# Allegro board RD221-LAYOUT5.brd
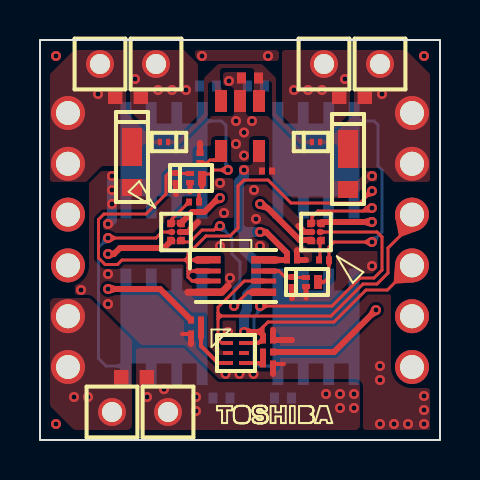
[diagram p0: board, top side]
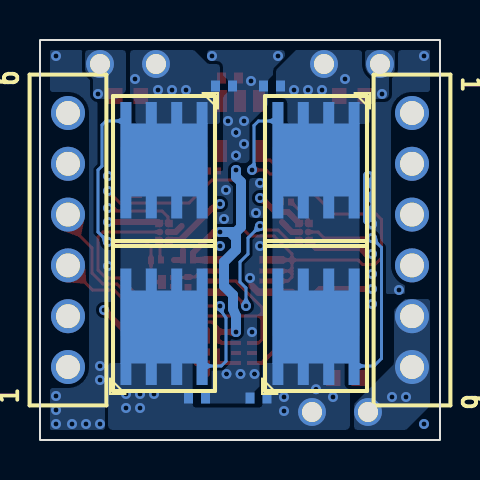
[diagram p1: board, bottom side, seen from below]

Outline 20 x 20 mm; copper layers: TOP, CONDUCTIVE2, CONDUCTIVE3, BOTTOM. Coordinates in mm from the lower left corner of the outline.
Outline path: rectangle 0,0 20,20

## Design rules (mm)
constraint set DEFAULT: 

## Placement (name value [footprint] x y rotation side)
C501  -  [KC00051KD]  10.5 18.1 180 top
C502  -  [KC00540KD]  8 14.1 90 top
C503  -  [KC00540KD]  11.35 13.45 0 top
C504  -  [KC00051KD]  8.4 17.7 0 bottom
C505  -  [KC00051KD]  12.15 2.1 180 bottom
C506  -  [KC00540KD]  11.4 5 0 top
C507  -  [KC00051KD]  10.8 17.7 180 bottom
C508  -  [KC00051KD]  9.07 2.1 0 bottom
C509  -  [KC00540KD]  12.6 9 0 top
CN501  -  [CU12000TD]  1.4 16.35 270 bottom
CN502  -  [CU12000TD]  18.6 3.65 90 bottom
D501  -  [MM02020KD]  4.6 13.9 90 top
D502  -  [MM02020KD]  15.4 13.8 90 top
D503  -  [KC10480CD]  6.2 14.9 0 top
D504  -  [KC10480CD]  13.8 14.9 180 top
DP501  -  [DP002X0KD]  3 18.8 0 top
DP502  -  [DP002X0KD]  5.8 18.8 0 top
DP503  -  [DP002X0KD]  17 18.8 0 top
DP504  -  [DP002X0KD]  14.2 18.8 0 top
DP505  -  [DP002X0KD]  6.4 1.4 0 top
DP506  -  [DP002X0KD]  3.6 1.4 0 top
IC501  -  [MM00631KD]  10 15.7 180 top
IC502  -  [DIC8T60KD]  9.8 8.2 270 top
IC503  -  [LA10251KD]  9.8 4.35 270 top
IC504  -  [BA10620KD]  6.8 10.4 270 top
IC505  -  [BA10620KD]  13.8 10.4 90 top
JP501  -  [KC00081KD]  4.4 17.2 0 top
JP502  -  [KC00081KD]  15.6 17.2 180 top
JP503  -  [KC00081KD]  4.7 3.1 180 top
NOREF  -  []  8 0 0 top
Q501  -  [LA10710KD]  7.8 13.1 0 top
Q502  -  [LA10710KD]  13.6 7.9 0 top
Q503  -  [SN10261KD]  6.2 13.45 0 bottom
Q504  -  [SN10261KD]  6.2 6.2 180 bottom
Q505  -  [SN10261KD]  13.8 13.45 0 bottom
Q506  -  [SN10261KD]  13.8 6.2 180 bottom
R501  -  [KC00540KD]  7.8 6 0 top
R502  -  [KC00540KD]  7.8 5.3 180 top
R503  -  [KC00540KD]  11.4 4.4 180 top
R504  -  [KC00540KD]  11.4 3.8 0 top
R505  -  [KC00540KD]  7.7 11.9 180 top
R506  -  [KC00540KD]  14.2 9 180 top
R507  -  [KC00540KD]  6.8 13.1 270 top
R508  -  [KC00540KD]  12.6 7.9 270 top

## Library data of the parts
C501 C504 C505 C507 C508 = DP0000016125
C502 C503 = DP0007093000
C506 C509 = DP0000015403
CN501 CN502 = DP0010563000
D501 = DP0010557000
D502 = DP0010580000
D503 D504 = DP0010560000
DP501-DP506 = DP9000817000
IC501 = DP0010585000
IC502 = DP0001429000
IC503 = DP0010561000
IC504 = DP0010596000
IC505 = DP0010597000
JP501-JP503 = DP0001376000
Q501 = DP0010564000
Q502 = DP0010513000
Q503-Q506 = DP0010567000
R501 = DP0000151167
R502 = DP0000151152
R503 = DP0000152120
R504 = DP0000151132
R505 R506 = DP0000155124
R507 R508 = DP0002867000

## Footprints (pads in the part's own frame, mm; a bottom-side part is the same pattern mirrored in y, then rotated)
BA10620KD
  round 0.325 smd: A1(-0.4,-0.2) A2(-0.4,0.2) B1(0,-0.2) B2(0,0.2) C1(0.4,-0.2) C2(0.4,0.2)
CU12000TD
  round 1.7 hole 1.2: 1(0,0) 2(2.54,0) 3(5.08,0) 4(7.62,0) 5(10.16,0) 6(12.7,0)
DIC8T60KD
  rect 0.375x1.24 smd: 1(-0.812,-1.385) 4(0.812,-1.385) 5(0.812,1.385) 8(-0.812,1.385)
  rect 0.25x1.24 smd: 2(-0.25,-1.385) 3(0.25,-1.385) 6(0.25,1.385) 7(-0.25,1.385)
DP002X0KD
  round 1.397 hole 1: 1(0,0)
KC00051KD
  rect 0.45x0.55 smd: 1(-0.425,0) 2(0.425,0)
KC00081KD
  rect 0.72x0.8 smd: 1(-0.64,0) 2(0.64,0)
KC00540KD
  rect 0.3x0.35 smd: 1(-0.25,0) 2(0.25,0)
KC10480CD
  rect 0.21x0.32 smd: A(-0.205,0) C(0.205,0)
LA10251KD
  rect 0.2x0.5 smd: 1(-0.5,-0.4) 2(0,-0.4) 3(0.5,-0.4) 4(0.5,0.4) 5(0,0.4) 6(-0.5,0.4)
LA10710KD
  rect 0.4x0.7 smd: D(0.3,0)
  rect 0.4x0.25 smd: G(-0.3,0.225) S(-0.3,-0.225)
MM00631KD
  rect 0.6x1.1 smd: 1(-0.95,-1.25) 2(0,-1.25) 3(0.95,-1.25) 4(0.95,1.25) 5(-0.95,1.25)
MM02020KD
  rect 0.85x1 smd: A(-1.275,0)
  rect 1.9x1 smd: C(0.75,0)
SN10261KD
  rect 0.55x1.1 smd: 1(-1.905,-2.9) 2(-0.635,-2.9) 3(0.635,-2.9) 4(1.905,-2.9)
  custom 1.09x1.09 smd: 5(0,0)

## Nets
GND: C501.2 C502.2 C503.2 C504.2 C505.2 C506.2 C507.2 C508.2 C509.2 CN501.3 CN501.4 D501.A D502.A IC501.2 IC502.4 IC503.2 IC504.B2 IC505.B2 Q501.S Q502.S R502.2 R504.2 R507.2 R508.2
VINA: CN501.1 CN501.2 D501.C D503.A DP501.1 JP501.1 R501.1
VINB: CN502.5 CN502.6 D502.C D504.A DP503.1 JP502.1 R503.1
EN20V: CN502.1 IC502.1 IC502.2 IC502.3 Q501.G R507.1
FLAG: CN502.4 IC502.6 IC503.1
LDO-VOUT: C503.1 C506.1 C509.1 CN502.3 IC501.5 IC502.8 IC503.6
SIG188: IC504.A1 R505.2
SIG189: IC505.B1 Q506.4
SIG190: IC505.A1 R506.2
SIG191: C507.1 DP504.1 IC505.A2 JP502.2 Q505.1 Q505.2 Q505.3
SIG192: C502.1 IC501.4
SIG193: C501.1 D503.C D504.C IC501.1 IC501.3
SIG194: IC503.4 R503.2 R504.1
SIG201: C505.1 C508.1 DP505.1 IC504.C1 IC505.C1 JP503.1 Q504.1 Q504.2 Q504.3 Q506.1 Q506.2 Q506.3
SIG202: IC502.7 Q502.G R508.1
SIG203: C504.1 DP502.1 IC504.A2 JP501.2 Q503.1 Q503.2 Q503.3
SIG204: Q501.D Q503.4 R505.1
SIG205: Q503.5 Q504.5
SIG206: IC504.B1 Q504.4
SIG207: IC502.5 IC504.C2
SIG208: Q505.5 Q506.5
SIG209: Q502.D Q505.4 R506.1
SIG211: IC503.3 R501.2 R502.1
VCT5V: CN502.2 IC505.C2
VOUT: CN501.5 CN501.6 DP506.1 JP503.2

Pads without a net: IC503 5

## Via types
v1: diameter 0.5, hole 0.25, TOP to BOTTOM, 77 vias

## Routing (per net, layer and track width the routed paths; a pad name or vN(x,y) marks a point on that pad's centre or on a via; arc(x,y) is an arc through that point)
GND: length 22.1
  TOP w0.2: 12.2,3.8 R504.2 ; R502.2 7.1,5.3
  TOP w0.25: Q502.S 13.3,7.1 ; Q501.S 7.5,12.4
  TOP w0.3: IC505.B2 13.22,10.4 12.92,10.7 ; R502.2 7.55,4.8 ; 7.9,10.9 7.4,10.4 IC504.B2 ; C502.2 8,14.85 ; R504.2 11.65,3.3 ; 12.85,9.49 C509.2 13.3,9 ; 11.65,5.5 C506.2 12.6,5 ; R508.2 12.6,7.1 ; R507.2 6.8,12.3
  TOP w0.35: 7.4,7.39 IC502.4 9.09,7.39 9.41,7.71
  CONDUCTIVE2 w0.15: 6.15,0.57 6.67,0.57 ; 3.35,0.57 3.9,0.57
  CONDUCTIVE2 w1: CN501.3 2.5,11.27 ; CN501.3 CN501.4 ; CN501.3 1.4,12.45 ; CN501.4 2.4,8.73 ; CN501.4 1.4,7.55
  CONDUCTIVE3 w0.15: 6.17,0.57 6.62,0.57
  BOTTOM w0.5: v1(3.6,13.2) v1(3.6,12.5) v1(3.6,11.8) 3.6,11 v1(3.4,10.8)
  vias: v1(0.8,19.2) v1(0.8,0.8) v1(2.05,7.5) v1(3.4,8.3) v1(3.4,6.8) v1(8.1,19.2) v1(9,12.85) v1(9,9.7) v1(9.2,11.35) v1(9.28,3.3) v1(9.45,17.95) v1(9.4,5.4) v1(9.5,8.1) v1(9.8,15.95) v1(9.8,14.8) v1(9.97,3.3) v1(10.2,15.38) v1(10.2,14.22) v1(10.6,15.95) v1(10.7,12.5) v1(10.68,3.3) v1(10.8,11.05) v1(11,9.7) v1(11.4,19.2) v1(16.6,13.2) v1(16.6,8.7) v1(17,3.7) v1(17,3) v1(17,0.8) v1(17.7,0.8) v1(18.4,0.8) v1(19.2,19.2) v1(19.2,2.2) v1(19.2,1.5) v1(19.2,0.8)
VINA: length 15.2
  TOP w0.3: R501.1 6,7.55 v1(3.4,7.55)
  CONDUCTIVE3 w0.6: v1(3.4,7.55) 3.05,7.55 2.65,7.95 2.65,17.05 v1(2.9,17.3)
VINB: length 17.2
  TOP w0.3: v1(16.8,6.5) 14.7,4.4 R503.1
  CONDUCTIVE3 w0.6: v1(17.1,17.3) 17.35,16.79 17.35,6.85 17,6.5 v1(16.8,6.5)
EN20V: length 41.2
  TOP w0.15: 7.83,7.95 7.6,7.95 7.4,8.15 7.4,8.3 ; 7.55,8.45 7.4,8.6 ; 7.55,8.45 7.4,8.3 ; 7.55,8.45 7.83,8.45 ; 7.55,8.45 7.4,8.45 ; 7.4,8.6 7.4,8.85 ; 7.4,8.6 7.4,8.45 ; 7.4,8.85 7.4,9 ; 7.4,8.85 7.55,9 ; 7.4,8.85 7.25,9 ; 7.4,9 7.55,9 ; 7.4,9 7.4,9.15 ; 7.4,9 7.25,9 ; 7.4,8.3 7.4,8.45 ; 7.42,13.32 7.1,13.32 R507.1 6.45,13.35 6.3,13.2 6.3,12.3 5.3,11.3 3.2,11.3 2.92,11.03 2.92,9.1 3.25,8.78 3.88,8.78 4.1,9 7.25,9 ; 7.55,9 7.87,9 ; 7.55,9 7.4,9.15 ; v1(16.6,12.45) 16,11.85 12.55,11.85 11.4,13 10.2,13 9.9,12.7 9.9,10.6 9.5,10.2 8.3,10.2 7.4,9.3 7.4,9.15 ; 7.25,9 7.4,9.15
  TOP w0.25: Q501.G 7.42,13.32 ; 7.83,7.95 IC502.3 ; 7.83,8.45 IC502.2
  TOP w0.35: 7.87,9 8.4,9
  CONDUCTIVE2 w0.15: CN502.1 17.25,5 17.25,9.9 16.7,10.45 16.35,10.45 16.05,10.75 16.05,11.9 v1(16.6,12.45)
FLAG: length 18.2
  TOP w0.15: 8.9,6.2 9.05,6.2 ; 8.9,6.2 8.9,6.05 ; 8.9,6.2 8.9,6.35 ; 9.05,6.2 8.9,6.05 ; 9.05,6.2 8.9,6.35 ; 9.05,6.2 14.55,6.2 16.15,7.8 16.85,7.8 17.4,8.35 17.4,9.6 18,10.2 CN502.4 ; 8.9,6.05 8.9,5.03 9.07,4.85 9.25,4.85 ; 10.69,7.95 10.22,7.95 8.9,6.63 8.9,6.35
  TOP w0.2: 9.25,4.85 IC503.1
  TOP w0.25: IC502.6 10.69,7.95
LDO-VOUT: length 24.9
  TOP w0.15: CN502.3 17.37,7.5 16.3,7.5 14.7,5.9 11.4,5.9 11.15,5.65 ; 11.15,5.65 11.15,5.35 ; 11.15,5.65 10.9,5.4
  TOP w0.2: IC503.6 10.9,4.85 C506.1
  TOP w0.3: 11.79,9 C509.1 12.35,9.36 11.31,10.4 v1(11,10.4) ; v1(10.2,5.4) 11,5.4 11.15,5.25 C506.1
  TOP w0.35: 11.79,9 11.19,9
  BOTTOM w0.5: v1(10.2,5.4) 10.2,6.2 10.35,6.55 10.35,7.25 10.8,7.7 10.8,8.9 10.2,9.5 10.2,10.1 ; 10.2,10.4 9.95,10.65 9.95,12.9 10.2,13.15 v1(10.2,13.5) ; 10.2,10.4 10.2,10.1 ; 10.2,10.4 10.5,10.4 ; 10.2,10.1 10.5,10.4 ; 10.5,10.4 v1(11,10.4)
SIG188: length 1.5
  TOP w0.15: R505.2 6.6,11.05 IC504.A1
SIG189: length 15.8
  TOP w0.15: IC505.B1 16.85,10.4 17.1,10.15 17.1,8.5 16.7,8.1 16,8.1 14.6,6.7 v1(11,6.7)
  BOTTOM w0.15: 11.67,3.7 10.94,3.7 10.7,3.94 10.7,6.1 10.9,6.4 v1(11,6.7)
  BOTTOM w0.3: 11.67,3.7 11.89,3.7
SIG190: length 1
  TOP w0.15: IC505.A1 14,9.2 R506.2
SIG191: length 9.9
  TOP w0.3: v1(11,11.8) 11.4,11.58 12.98,10 IC505.A2
  CONDUCTIVE3 w0.6: v1(11,11.8) 11.3,11.8 11.9,12.4 11.9,16.7 v1(12.7,17.5)
  vias: v1(13.4,17.5) v1(14.1,17.5) v1(15.25,18.05)
SIG192: length 1.1
  TOP w0.15: 8.02,13.85 8.35,13.85 8.5,14 8.77,14
  TOP w0.2: 8.77,14 9,14
  TOP w0.3: C502.1 8.02,13.85
SIG194: length 1.6
  TOP w0.2: IC503.4 10.9,3.85 R504.1
  TOP w0.3: R503.2 R504.1
SIG201: length 28.1
  TOP w0.3: v1(3.4,9.3) 3.7,9.3 4,9.6 6.2,9.6 IC504.C1 ; v1(16.6,10.9) 14.1,10.9 IC505.C1
  CONDUCTIVE3 w0.5: v1(5.35,2.15) 5.35,8.35 ; 5.35,8.35 5.35,9.1 ; 5.35,8.35 5.9,8.9 ; 5.35,9.1 5.55,8.9 5.9,8.9 ; 5.35,9.1 5.15,9.3 v1(3.4,9.3) ; 5.9,8.9 11.3,8.9 13.3,10.9 v1(16.6,10.9)
  vias: v1(6.2,2.54) v1(7.8,2.15) v1(7.8,1.45) v1(14.3,2.3) v1(15,2.3) v1(15,1.6) v1(15.7,2.3) v1(15.7,1.6)
SIG202: length 2.2
  TOP w0.15: 11.77,8.45 11.95,8.45 12.25,8.15 R508.1 12.9,8.12 13.22,8.12
  TOP w0.25: Q502.G 13.22,8.12 ; 11.77,8.45 IC502.7
SIG203: length 8.9
  TOP w0.3: IC504.A2 7.6,11.4 8.22,11.4 8.74,11.92 v1(9,12.1)
  CONDUCTIVE3 w0.6: v1(9,12.1) 8.6,12.1 8.2,12.5 8.2,16.6 v1(7.3,17.5)
  vias: v1(4.75,18.05) v1(5.9,17.5) v1(6.6,17.5)
SIG204: length 6.2
  TOP w0.15: 8.1,13.3 8.5,13.3 8.7,13.5 v1(9.4,13.5) ; 7.95,11.99 7.95,12.35 8.1,12.5 8.1,12.84
  TOP w0.3: R505.1 7.95,11.99
  TOP w0.4: 8.1,12.84 Q501.D
  BOTTOM w0.15: 8.33,15.95 9.07,15.95 9.3,15.72 9.3,13.8 v1(9.4,13.5)
  BOTTOM w0.3: 8.11,15.95 8.33,15.95
SIG206: length 11.1
  TOP w0.15: IC504.B1 6.1,10.4 5.8,10.1 v1(3.4,10.1)
  BOTTOM w0.15: 4.07,3.7 3.3,3.7 2.92,4.08 2.92,9.62 v1(3.4,10.1)
  BOTTOM w0.3: 4.07,3.7 4.29,3.7
SIG207: length 8.6
  TOP w0.15: v1(9.7,6.7) 10.39,7.39 10.65,7.39 ; v1(9,10.7) 8.7,10.5 8.1,10.5 7.5,9.9 7.25,9.9 IC504.C2
  TOP w0.37: 10.65,7.39 IC502.5
  BOTTOM w0.15: v1(9.7,6.7) 9.7,7.6 10,7.9 10,8.9 9.6,9.3 9.6,10.1 v1(9,10.7)
SIG209: length 11.8
  TOP w0.15: 14.45,9.02 14.45,9.65 14.7,9.9 v1(16.6,9.9) ; Q502.D 14.2,7.9 14.45,8.15 14.45,8.9
  TOP w0.3: 14.45,9.02 R506.1 14.45,8.9
  BOTTOM w0.15: 15.93,15.95 16.7,15.95 16.9,15.75 16.9,13.7 17.1,13.5 17.1,10.4 v1(16.6,9.9)
  BOTTOM w0.3: 15.71,15.95 15.93,15.95
SIG211: length 3
  TOP w0.2: 8.05,5.19 8.05,4.7 8.9,3.85 IC503.3
  TOP w0.3: R501.2 R502.1 8.05,5.19
VCT5V: length 10.3
  TOP w0.15: 16.15,11.45 16.45,11.45 v1(16.6,11.6) 16.3,11.6 16.15,11.45 ; 16.15,11.45 13.9,11.45 13.6,11.15 IC505.C2
  CONDUCTIVE2 w0.15: CN502.2 17.65,7.14 17.65,10.55 v1(16.6,11.6)
VOUT:
  vias: v1(1.7,2.15) v1(2.4,2.15)

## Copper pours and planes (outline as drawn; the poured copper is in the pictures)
GND on TOP: outline of 290 points within 1.74,0.5 19.5,18.4
GND on TOP: outline of 88 points within 7.93,7.4 13.6,12.78
GND on TOP: 8.02,18.95 7.92,18.99 7.79,19.12 7.75,19.22 7.75,19.35 7.79,19.46 7.9,19.5 11.8,19.5 11.91,19.46 11.95,19.35 11.95,19.1 11.91,18.99 11.8,18.95
GND on TOP: 3.79,10.35 3.77,10.35 3.75,10.36 3.5,10.49 3.4,10.5 3.3,10.5 3.19,10.54 3.15,10.65 3.15,10.9 3.16,10.93 3.17,10.95 3.27,11.05 3.3,11.07 3.32,11.07 5.3,11.07 5.39,11.09 5.46,11.14 6.46,12.14 6.52,12.24 6.53,12.3 6.53,12.35 6.57,12.46 6.67,12.5 7.55,12.5 7.6,12.48 7.62,12.43 7.62,12.35 7.6,12.3 7.55,12.28 7.33,12.28 7.17,12.21 7.1,12.05 7.1,11.9 7.09,11.87 7.08,11.85 6.44,11.21 6.4,11.17 6.38,11.16 6.26,11.08 6.21,10.94 6.21,10.91 6.2,10.89 6.19,10.86 5.7,10.37 5.67,10.36 5.64,10.35
GND on TOP: 7.44,10.25 7.38,10.27 7.36,10.33 7.36,10.58 7.38,10.64 7.39,10.67 7.4,10.7 7.42,10.72 7.51,10.79 7.8,11.08 7.83,11.09 7.86,11.1 8.22,11.1 8.34,11.12 8.43,11.19 8.89,11.64 8.92,11.66 9.11,11.71 9.4,12.15 9,12.5 8.75,12.5 8.64,12.54 8.6,12.65 8.6,12.89 8.61,12.95 8.64,12.99 8.71,13.06 8.81,13.1 9.53,13.1 9.63,13.06 9.68,12.95 9.68,11.19 9.67,11.16 9.65,11.14 9.6,11.11 9.55,11.1 9,11.1 8.8,11.05 8.65,10.9 8.62,10.82 8.6,10.78 8.58,10.74 8.53,10.72 8.1,10.72 8.01,10.71 7.94,10.66 7.58,10.3 7.53,10.26 7.47,10.25
GND on BOTTOM: 8.9,11.1 8.79,11.14 8.75,11.25 8.75,11.55 8.79,11.66 8.9,11.7 9,11.7 9.28,11.82 9.4,12.1 9.4,12.1 9.28,12.38 9,12.5 8.9,12.5 8.79,12.54 8.75,12.65 8.75,12.95 8.79,13.06 8.9,13.1 9.4,13.1 9.51,13.06 9.55,12.95 9.55,12.1 9.55,12.1 9.55,11.25 9.51,11.14 9.4,11.1
GND on BOTTOM: 9.43,1.82 9.32,1.87 9.28,1.98 9.28,2.42 9.05,2.65 9.03,2.68 9.03,2.71 9.03,3.78 9.04,3.83 9.13,3.87 9.15,3.91 9.15,6.12 9.13,6.18 9.07,6.2 8.82,6.2 8.77,6.22 8.75,6.28 8.75,10.26 8.78,10.32 8.85,10.33 8.9,10.31 9.11,10.26 9.15,10.24 9.35,10.03 9.37,10 9.38,9.98 9.38,9.3 9.39,9.21 9.44,9.14 9.75,8.83 9.77,8.8 9.78,8.78 9.78,8.02 9.77,8 9.75,7.97 9.54,7.76 9.49,7.69 9.47,7.6 9.47,7.13 9.46,7.09 9.35,6.9 9.36,6.49 9.72,6.3 9.78,6.28 9.8,6.23 9.8,5.4 9.98,5.06 10.44,5.03 10.47,4.97 10.47,3.94 10.49,3.85 10.54,3.78 10.78,3.54 10.85,3.49 10.94,3.48 11.35,3.48 11.4,3.45 11.42,3.4 11.42,2.65 11.5,2.46 11.7,2.38 11.88,2.38 11.93,2.35 11.95,2.3 11.95,1.9 11.93,1.85 11.88,1.82
GND on BOTTOM: 1.83,7.3 1.78,7.32 1.75,7.38 1.75,7.69 1.77,7.73 1.8,7.76 2.28,8.15 2.45,8.75 2.45,11.25 2.45,11.29 2.45,13.79 2.45,13.83 2.45,16.33 2.15,17.09 1.4,17.4 0.65,17.4 0.54,17.44 0.5,17.55 0.5,19.43 0.52,19.48 0.57,19.5 1.95,19.5 2.06,19.46 2.1,19.35 2.1,18.51 2.14,18.36 2.19,18.3 2.38,18.11 2.39,18.09 2.4,18.06 2.4,17.3 2.52,17.02 2.8,16.9 3.17,16.9 3.23,16.88 3.25,16.82 3.25,13.53 3.27,13.47 3.33,13.45 3.58,13.45 3.63,13.43 3.65,13.38 3.65,10.65 3.61,10.54 3.5,10.5 3.4,10.5 3.16,10.42 3.01,10.2 2.96,9.99 2.94,9.95 2.77,9.78 2.72,9.71 2.7,9.62 2.7,7.38 2.68,7.32 2.62,7.3
GND on BOTTOM: 16.9,0.5 16.79,0.54 16.75,0.65 16.75,6.03 16.77,6.08 16.82,6.1 17.2,6.51 16.8,6.9 16.5,6.9 16.39,6.94 16.35,7.05 16.35,9.43 16.37,9.48 16.43,9.5 16.6,9.5 16.84,9.58 16.99,9.79 17.04,10.01 17.06,10.05 17.26,10.24 17.3,10.3 17.32,10.38 17.32,13.5 17.31,13.59 17.26,13.66 17.15,13.77 17.13,13.8 17.12,13.82 17.13,16.84 17.14,16.88 17.41,17.05 17.5,17.3 17.5,17.96 17.51,17.99 17.52,18.01 17.81,18.3 17.88,18.4 17.9,18.51 17.9,19.35 17.89,19.41 17.91,19.47 17.97,19.5 19.43,19.5 19.48,19.48 19.5,19.43 19.5,17.55 19.46,17.44 19.35,17.4 18.6,17.4 17.86,17.09 17.55,16.35 17.55,3.65 17.86,2.91 18.6,2.6 19.35,2.6 19.46,2.56 19.5,2.45 19.5,0.57 19.48,0.52 19.43,0.5
GND on BOTTOM: 10.43,10.8 10.37,10.82 10.35,10.88 10.35,12.65 10.36,12.68 10.37,12.71 10.48,12.82 10.57,12.95 10.6,13.1 10.6,13.5 10.41,13.84 10.02,13.86 9.98,13.85 9.74,13.85 9.68,13.86 9.63,13.89 9.57,13.96 9.54,14 9.53,14.06 9.53,15.58 9.53,15.72 9.51,15.81 9.46,15.88 8.64,16.7 8.61,16.74 8.6,16.93 8.6,17.94 8.56,18.04 8.37,18.23 8.36,18.25 8.35,18.28 8.35,18.44 8.31,18.59 8.26,18.65 7.79,19.12 7.75,19.22 7.75,19.35 7.79,19.46 7.9,19.5 11.5,19.5 11.61,19.46 11.65,19.35 11.65,19.16 11.61,19.06 11.54,18.99 11.44,18.95 11.15,18.95 11,18.91 10.89,18.8 10.85,18.65 10.85,18.28 10.84,18.25 10.83,18.23 10.64,18.04 10.6,17.94 10.6,17.46 10.61,17.4 10.64,17.36 10.81,17.19 10.84,17.15 10.85,13.53 10.87,13.47 10.93,13.45 11.18,13.45 11.23,13.43 11.25,13.38 11.25,12.35 11.21,12.24 11.1,12.2 11,12.2 10.6,11.8 11,11.4 11.1,11.4 11.21,11.36 11.25,11.25 11.25,10.95 11.21,10.84 11.1,10.8
GND on CONDUCTIVE2: outline of 156 points within 0.5,0.5 19.5,19.5 ; 22 cut-outs
GND on CONDUCTIVE3: outline of 114 points within 0.5,0.5 19.5,10.5 ; 6 cut-outs
GND on CONDUCTIVE3: outline of 103 points within 0.5,9.3 19.5,19.5 ; 7 cut-outs
VINA on BOTTOM: 2.8,17.05 2.62,17.12 2.55,17.3 2.55,18.09 2.51,18.19 2.29,18.41 2.25,18.51 2.25,19.35 2.29,19.46 2.4,19.5 3.6,19.5 3.7,19.47 3.75,19.38 3.75,19.35 3.75,18.8 3.67,18.46 3.37,18.12 3.35,18.01 3.35,17.2 3.31,17.09 3.2,17.05
VINB on BOTTOM: 16.16,17.05 16.06,17.09 15.74,17.41 15.7,17.51 15.7,19.35 15.74,19.46 15.85,19.5 17.6,19.5 17.71,19.46 17.75,19.35 17.75,18.51 17.71,18.41 17.39,18.09 17.35,17.99 17.35,17.3 17.32,17.18 17.23,17.08 17.1,17.05
LDO-VOUT on TOP: 10.1,13.25 9.99,13.29 9.95,13.4 9.95,13.6 9.99,13.71 10.1,13.75 10.49,13.75 10.55,13.76 10.59,13.79 10.61,13.81 10.65,13.91 10.65,14.75 10.69,14.86 10.8,14.9 11.1,14.9 11.21,14.86 11.25,14.75 11.25,13.4 11.21,13.29 11.1,13.25
SIG191 on TOP: 13.01,15.35 12.98,15.36 12.95,15.37 12.12,16.2 12.11,16.23 12.1,16.26 12.1,19.35 12.14,19.46 12.25,19.5 15.35,19.5 15.46,19.46 15.5,19.35 15.5,16.41 15.46,16.31 14.54,15.39 14.44,15.35
SIG191 on BOTTOM: 11.15,15.8 11.04,15.84 11,15.95 11,18.65 11.04,18.76 11.15,18.8 11.54,18.8 11.64,18.84 12.26,19.46 12.36,19.5 15.35,19.5 15.46,19.46 15.5,19.35 15.5,17.17 15.48,17.12 15.29,17 15.23,16.82 15.23,15.95 15.19,15.84 15.08,15.8
SIG193 on TOP: 6.38,14.8 6.32,14.82 6.3,14.88 6.3,14.93 6.32,14.98 6.38,15 6.83,15 6.88,15.01 6.93,15.04 8.16,16.27 8.19,16.32 8.2,16.37 8.2,18.04 8.24,18.14 8.86,18.76 8.96,18.8 11.04,18.8 11.14,18.76 11.76,18.14 11.8,18.04 11.8,16.37 11.81,16.32 11.84,16.27 13.12,15.01 13.17,15 13.62,15 13.68,14.98 13.7,14.93 13.7,14.88 13.68,14.82 13.62,14.8 13.06,14.8 13,14.81 12.96,14.84 11.64,16.16 11.61,16.2 11.6,16.26 11.6,17.8 11.56,17.91 11.45,17.95 11.3,17.95 11.19,17.91 11.15,17.8 11.15,16.79 11.12,16.72 11.05,16.69 10.8,16.69 10.73,16.72 10.7,16.79 10.7,18.45 10.66,18.56 10.55,18.6 9.15,18.6 9.04,18.56 9,18.45 9,17.71 9.01,17.65 9.04,17.61 9.31,17.34 9.34,17.3 9.35,17.24 9.35,16.77 9.33,16.72 9.28,16.7 8.82,16.7 8.77,16.72 8.75,16.77 8.75,17.75 8.71,17.86 8.6,17.9 8.55,17.9 8.44,17.86 8.4,17.75 8.4,16.26 8.39,16.2 8.36,16.16 7.04,14.84 7,14.81 6.94,14.8
SIG201 on TOP: 5.05,0.5 4.92,0.53 4.83,0.62 4.8,0.75 4.8,4.45 4.84,4.56 4.95,4.6 7.16,4.6 7.19,4.59 7.21,4.58 8.81,2.97 8.93,2.91 8.99,2.9 15.75,2.9 15.93,2.83 16,2.65 16,0.75 15.93,0.57 15.75,0.5
SIG201 on BOTTOM: 4.75,0.5 4.57,0.57 4.5,0.75 4.5,2.48 4.52,2.53 4.56,2.56 4.71,2.65 4.77,2.83 4.77,3.77 4.79,3.83 4.84,3.85 8.72,3.85 8.83,3.81 8.88,3.7 8.88,1.77 8.92,1.67 9.03,1.62 12.22,1.62 12.33,1.67 12.37,1.77 12.37,3.77 12.39,3.83 12.45,3.85 16.45,3.85 16.56,3.81 16.6,3.7 16.6,0.75 16.53,0.57 16.35,0.5
SIG201 on CONDUCTIVE3: 7.65,1.15 7.54,1.19 7.5,1.3 7.5,2.45 7.54,2.56 7.65,2.6 15.85,2.6 15.96,2.56 16,2.45 16,1.3 15.96,1.19 15.85,1.15
SIG203 on TOP: 4.54,16.41 4.51,16.45 4.5,16.51 4.5,19.35 4.54,19.46 4.65,19.5 7.14,19.5 7.24,19.46 7.86,18.84 7.9,18.74 7.9,16.26 7.89,16.23 7.88,16.2 7.05,15.37 7.02,15.36 6.99,15.35 5.66,15.35 5.6,15.36 5.56,15.39
SIG203 on BOTTOM: 3.65,15.8 3.54,15.84 3.5,15.95 3.5,18.01 3.51,18.05 3.8,18.39 3.9,18.8 3.9,19.35 3.94,19.46 4.05,19.5 7.17,19.5 7.2,19.49 7.22,19.48 8.16,18.54 8.2,18.44 8.2,17.25 8.16,17.14 8.05,17.1 7.91,17.1 7.77,17.06 7.67,16.96 7.63,16.82 7.63,15.95 7.59,15.84 7.48,15.8
SIG205 on BOTTOM: 4.17,5.1 4.07,5.14 4.03,5.25 4.03,14.6 4.07,14.71 4.17,14.75 8.22,14.75 8.33,14.71 8.38,14.6 8.38,5.25 8.33,5.14 8.22,5.1
SIG208 on BOTTOM: 11.78,5.1 11.67,5.14 11.62,5.25 11.62,14.6 11.67,14.71 11.78,14.75 15.82,14.75 15.93,14.71 15.97,14.6 15.97,5.25 15.93,5.14 15.82,5.1
VOUT on BOTTOM: 1.8,0.5 1.71,0.52 1.63,0.57 0.57,1.63 0.52,1.71 0.5,1.8 0.5,6.9 0.54,7.01 0.65,7.05 1.69,7.05 1.75,7.04 1.79,7.01 2.26,6.54 2.3,6.44 2.3,3.9 2.33,3.78 2.37,3.73 4.26,1.84 4.3,1.74 4.3,0.65 4.26,0.54 4.15,0.5

Small or netless copper shapes (teardrops, artwork), in the pictures only: 66 on TOP, 10 on BOTTOM, 4 on CONDUCTIVE2, 3 on CONDUCTIVE3

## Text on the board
Ref Des/Silkscreen Bottom: 1 | 6
SYMBOL-2-TOP: IC501 | IC502 | IC503 | MUX5 | D501 | IC504 | D502 | IC505 | VINA | VOUT | GND | FLAG | VINB
SYMBOL-2-BOTTOM: 1 | Q503 | Q504 | Q506 | Q505
User.5: 1 | 6
